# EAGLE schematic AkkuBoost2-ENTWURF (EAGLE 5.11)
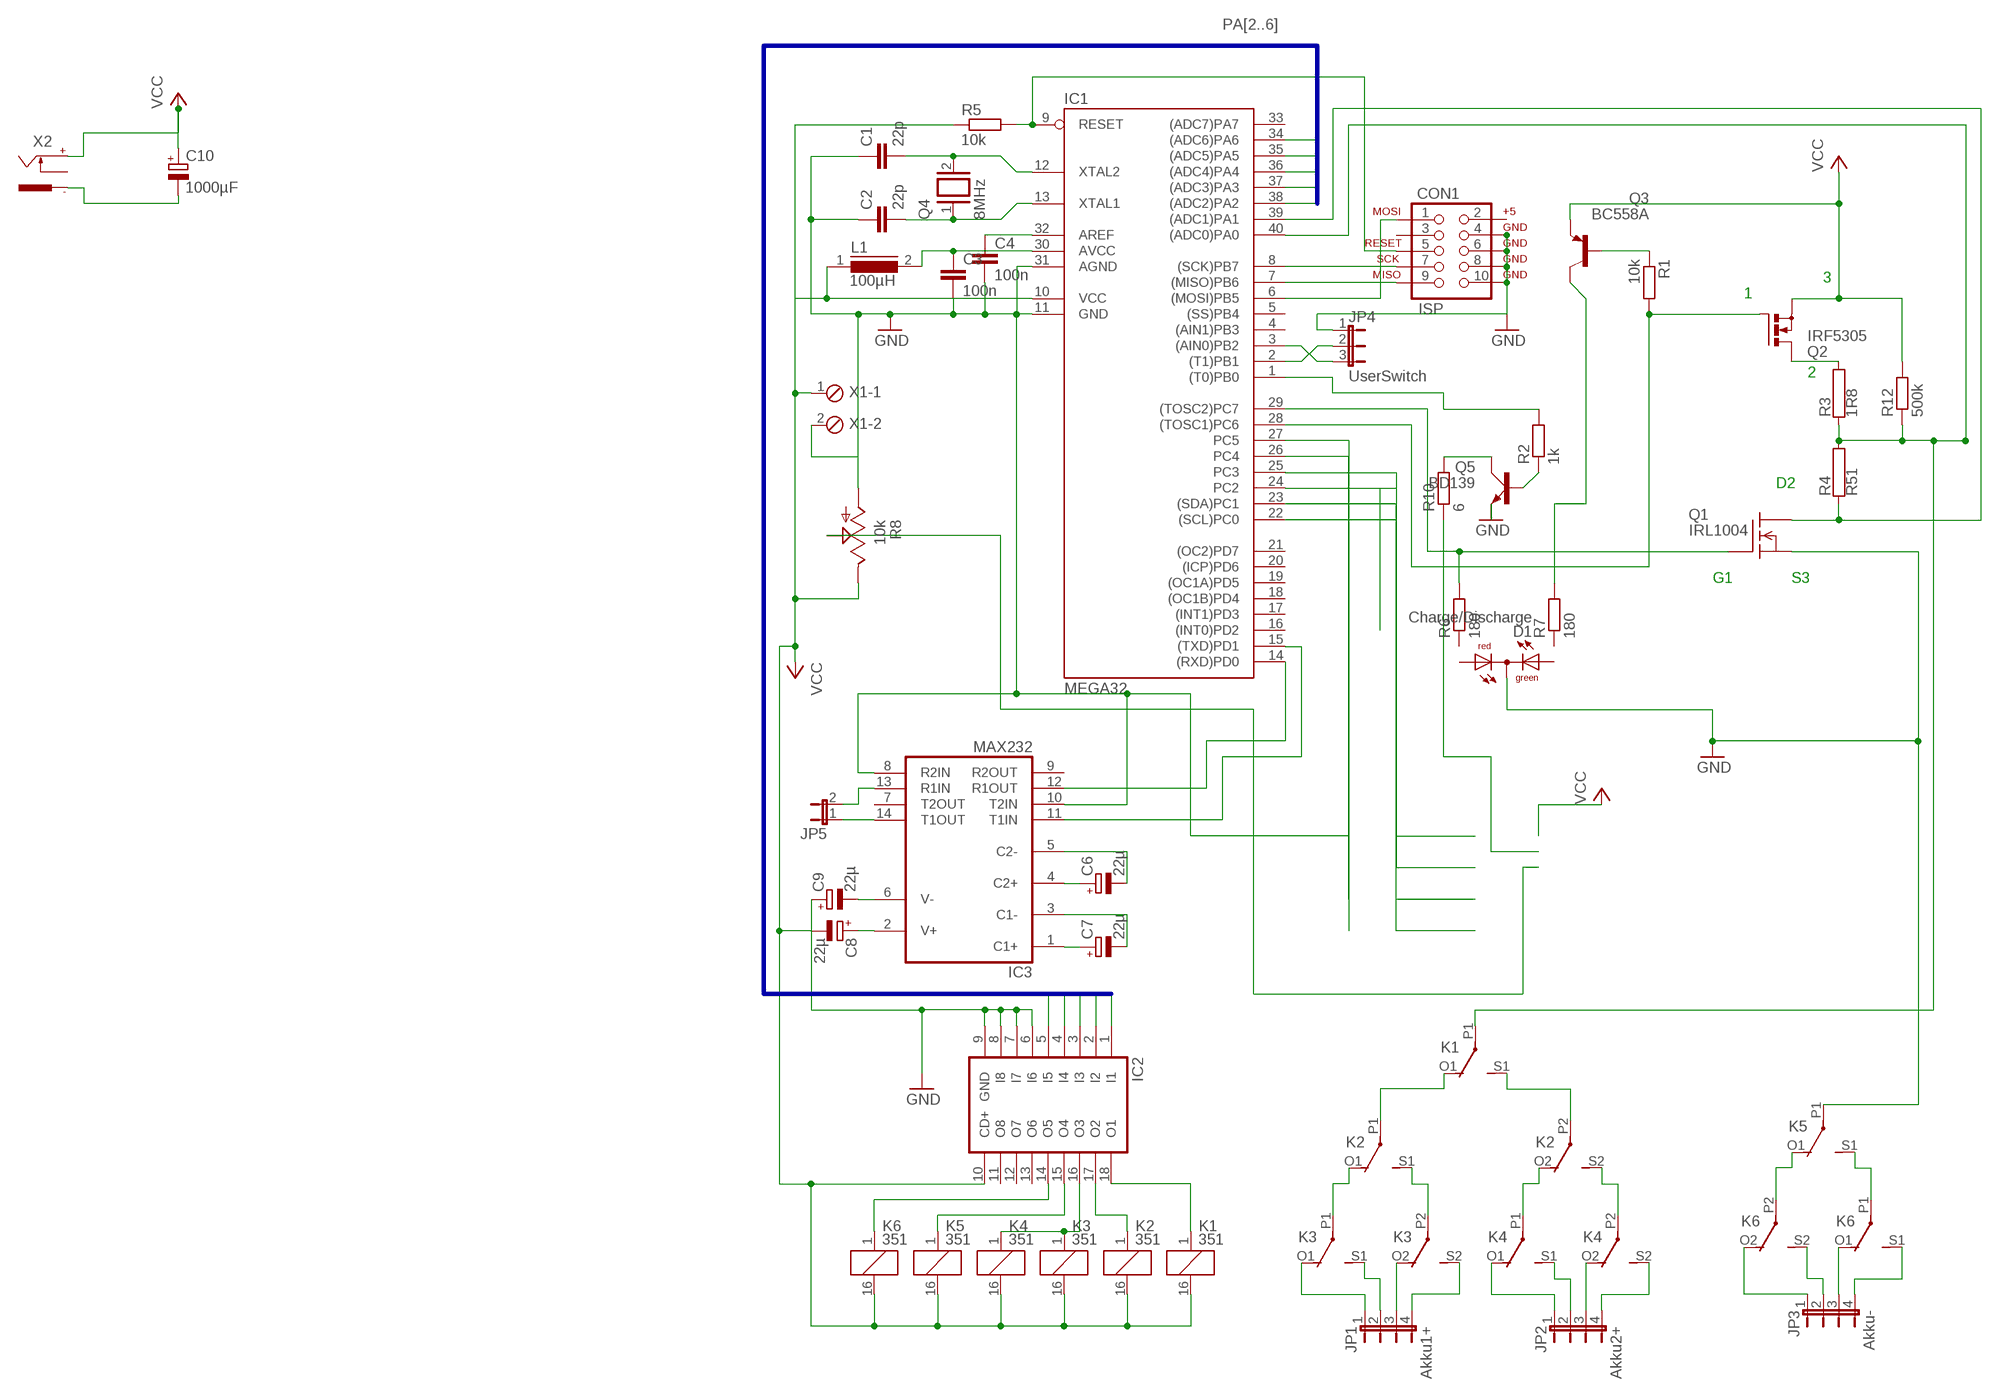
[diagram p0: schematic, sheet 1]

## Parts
C1  22p  C-EU050-024X044  [C050-024X044]
C2  22p  C-EU050-024X044  [C050-024X044]
C3  100n  C-EU050-025X075  [C050-025X075]
C4  100n  C-EU050-025X075  [C050-025X075]
C6  22µ  CPOL-EUE2.5-5  [E2,5-5]
C7  22µ  CPOL-EUE2.5-5  [E2,5-5]
C8  22µ  CPOL-EUE2.5-5  [E2,5-5]
C9  22µ  CPOL-EUE2.5-5  [E2,5-5]
C10  1000µF  CPOL-EUE5-13  [E5-13]
CON1  ISP  AVR_SPI_PROG2LOCK  [2X5-SHROUDED_LOCK]
D1  Charge/Discharge  DUOLED5MM  [DUOLED5MM]
IC1  MEGA32  MEGA163LP  [DIL40]
IC2  ULN2803A  [DIL18]
IC3  MAX232  [DIL16]
JP1  Akku1+  JP4E  [JP4]
JP2  Akku2+  JP4E  [JP4]
JP3  Akku-  JP4E  [JP4]
JP4  UserSwitch  JP2E  [JP2]
JP5  JP1E  [JP1]
K1  351  [351]
K2  351  [351]
K3  351  [351]
K4  351  [351]
K5  351  [351]
K6  351  [351]
L1  100µH  SMCC12  [SMCC12]
Q1  IRL1004  BUZ10  [TO220]
Q2  IRF5305  IRF512  [TO220BV]
Q3  BC558A  [TO92-EBC]
Q4  8MHz  XTAL/S  [QS]
Q5  BD139  [TO126AV]
R1  10k  R-EU_0207/7  [0207/7]
R2  1k  R-EU_0207/12  [0207/12]
R3  1R8  RKH214-8  [KH214-8]
R4  R51  RKH208-8  [KH208-8]
R5  10k  R-EU_0207/12  [0207/12]
R6  180  R-EU_0207/7  [0207/7]
R7  180  R-EU_0207/7  [0207/7]
R8  10k  TRIM_US-CA6H  [CA6H]
R10  6  R-EU_0207/10  [0207/10]
R12  500k  R-EU_0207/7  [0207/7]
X1  MPT2  [2POL254]
X2  737992-55  [737992-5]

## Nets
GND: C1.1 C2.1 C3.2 C4.2 C9.+ CON1.4 CON1.6 CON1.8 CON1.10 D1.K(C) IC1.11(GND) IC1.31(AGND) IC2.6(I6) IC2.7(I7) IC2.8(I8) IC2.9(GND) IC3.8(R2IN) IC3.10(T2IN) JP4.1 K5.P1(2:P) Q1.3(S) Q5.E R8.A X1.2
N$1: IC1.28((TOSC1)PC6) Q2.G R1.2
N$2: C1.2 IC1.12(XTAL2) Q4.2
N$3: C2.2 IC1.13(XTAL1) Q4.1
N$4: Q2.D R3.2
N$6: Q3.B R1.1
N$8: Q3.C R7.2
N$9: IC1.29((TOSC2)PC7) Q1.1(G) R6.2
N$10: IC1.40((ADC0)PA0) K1.P1(2:P) R3.1 R4.2 R12.1
N$11: IC1.39((ADC1)PA1) Q1.2(D) R4.1
N$12: CON1.1 IC1.6((MOSI)PB5)
N$13: CON1.5 IC1.9(RESET) R5.2
N$17: R8.S
N$18: IC1.1((T0)PB0) R2.2
N$19: Q5.B R2.1
N$20: IC1.26(PC4)
N$22: IC1.22((SCL)PC0)
N$23: IC1.27(PC5)
N$24: IC1.25(PC3)
N$25: IC1.24(PC2)
N$26: Q5.C R10.2
N$27: R10.1
N$28: IC2.18(O1) K1.1
N$29: IC2.17(O2) K2.1
N$30: IC2.16(O3) K3.1 K4.1
N$31: IC2.15(O4) K5.1
N$32: IC2.14(O5) K6.1
N$33: K1.O1(2:O) K2.P1(2:P)
N$34: K1.S1(2:S) K2.P2(3:P)
N$35: K2.O1(2:O) K3.P1(2:P)
N$36: K2.S1(2:S) K3.P2(3:P)
N$37: K2.O2(3:O) K4.P1(2:P)
N$38: K2.S2(3:S) K4.P2(3:P)
N$39: K5.O1(2:O) K6.P2(3:P)
N$40: K5.S1(2:S) K6.P1(2:P)
N$41: JP1.1 K3.O1(2:O)
N$43: JP1.3 K3.O2(3:O)
N$44: JP1.4 K3.S2(3:S)
N$45: JP2.1 K4.O1(2:O)
N$46: JP2.2 K4.S1(2:S)
N$47: JP2.3 K4.O2(3:O)
N$48: JP2.4 K4.S2(3:S)
N$49: JP3.1 K6.O2(3:O)
N$50: JP3.2 K6.S2(3:S)
N$51: JP3.3 K6.O1(2:O)
N$52: JP3.4 K6.S1(2:S)
N$53: C3.1 IC1.30(AVCC) L1.2
N$54: C4.1 IC1.32(AREF)
N$55: IC1.2((T1)PB1) JP4.2
N$56: IC1.3((AIN0)PB2) JP4.3
N$57: IC1.15((TXD)PD1) IC3.11(T1IN)
N$58: IC1.14((RXD)PD0) IC3.12(R1OUT)
N$59: C6.+ IC3.4(C2+)
N$60: C6.- IC3.5(C2-)
N$61: C7.+ IC3.1(C1+)
N$62: C7.- IC3.3(C1-)
N$63: C8.+ IC3.2(V+)
N$64: C9.- IC3.6(V-)
N$65: IC3.14(T1OUT) JP5.1
N$66: IC3.13(R1IN) JP5.2
N$74: JP1.2 K3.S1(2:S)
N$75: CON1.9 IC1.7((MISO)PB6)
N$76: CON1.7 IC1.8((SCK)PB7)
N$114: IC1.23((SDA)PC1)
N$119: C10.- X2.-1
PA2: IC1.38((ADC2)PA2) IC2.1(I1)
PA3: IC1.37((ADC3)PA3) IC2.2(I2)
PA4: IC1.36((ADC4)PA4) IC2.3(I3)
PA5: IC1.35((ADC5)PA5) IC2.4(I4)
PA6: IC1.34((ADC6)PA6) IC2.5(I5)
VCC: C8.- C10.+ IC1.10(VCC) IC2.10(CD+) K1.16 K2.16 K3.16 K4.16 K5.16 K6.16 L1.1 Q2.S Q3.E R5.1 R8.E R12.2 X1.1 X2.+
Unconnected: CON1.2 CON1.3 D1.AG D1.AR IC1.4((AIN1)PB3) IC1.5((SS)PB4) IC1.16((INT0)PD2) IC1.17((INT1)PD3) IC1.18((OC1B)PD4) IC1.19((OC1A)PD5) IC1.20((ICP)PD6) IC1.21((OC2)PD7) IC1.33((ADC7)PA7) IC2.11(O8) IC2.12(O7) IC2.13(O6) IC3.7(T2OUT) IC3.9(R2OUT) K1.O2(3:O) K1.P2(3:P) K1.S2(3:S) K5.O2(3:O) K5.P2(3:P) K5.S2(3:S) R6.1 R7.1 X2.-2 X2.K

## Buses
PA[2..6]

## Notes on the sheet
- 3
- 1
- 2
- D2
- G1 | S3

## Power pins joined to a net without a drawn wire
GND: IC3.15(GND)
VCC: IC3.16(VCC)

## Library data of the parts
C1-C4 = rcl:C-EU: CAPACITOR, European symbol
C6-C10 = rcl:CPOL-EU: POLARIZED CAPACITOR, European symbol
CON1 = SparkFun:AVR_SPI_PROG2: AVR ICSP Header This is the standard AVR In Circuit Serial Programming header. Minimal, but includes pin one indicator. Works with standard Olimex programmers. Also look for the 6-pin reduced version. Spark Fun Electronics SKU: PRT-00778
D1 = led:DUOLED5MM: DUO LED 2 colors, 5 mm, round
IC1 = atmel:MEGA163*P: MICROCONTROLLER 16 Kbytes FLASH 1 Kbytes EEPROM 1 Kbytes SRAM UART 8-channel 10 bit ADC hardware multiplier Source: avr.lbr; OC_FARNELL: unknown; OC_NEWARK: unknown
IC2 = uln-udn:ULN2803A: DRIVER ARRAY
IC3 = maxim:MAX232: RS232 TRANSEIVER; MF: MAXIM; MPN: MAX232ACPE+; OC_FARNELL: 9723773; OC_NEWARK: 68K4544
JP1-JP3 = jumper:JP4E: JUMPER
JP4 = jumper:JP2E: JUMPER
JP5 = jumper:JP1E: JUMPER
K1-K6 = relay:351: RELAY 2 x switch, Omron; OC_FARNELL: unknown; OC_NEWARK: unknown
L1 = inductors:SMCC12: INDUCTOR
Q1 = transistor-fet:BUZ10: N-Channel Enhancement MOSFET 50V; 20A; 0,080Ohm
Q2 = transistor-power:IRF512: N-CHANNEL MOS FET
Q3 = transistor-pnp:BC558*: PNP Transistror
Q4 = special:XTAL/S: CRYSTAL
Q5 = transistor-power:BD139: NPN TRANSISTOR
R1 R5-R7 R10 R12 = rcl:R-EU_: RESISTOR, European symbol
R2 = resistor:R-EU_: RESISTOR, European symbol
R3 R4 = resistor-power:R: Power Resitor; OC_FARNELL: unknown; OC_NEWARK: unknown
R8 = pot:TRIM_US-: POTENTIOMETER
X1 = con-phoenix-254:MPT2: PHOENIX CONNECTOR; OC_FARNELL: unknown; OC_NEWARK: unknown
X2 = con-conrad:737992-55: FEMALE PRINT CONNECTOR DIN 45323 (34V/3A), ROKA, distributor Conrad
